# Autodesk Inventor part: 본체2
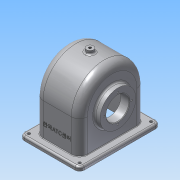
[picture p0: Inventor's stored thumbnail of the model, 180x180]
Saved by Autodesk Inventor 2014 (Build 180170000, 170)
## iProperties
Created: 2016-01
Part Number: 본체2
Material: 알루미늄 6061
Document SubType Name: Modeling
Designer: User
Mass: 842.835 g
Surface Area: 990.698 cm^2
Volume: 311.009 cm^3
Density: 2.71 g/cm^3
Appearance: 알루미늄 - 평지
Author: User
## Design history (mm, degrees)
sketch "스케치1"
  geometry: L1 (-57, 0)-(57, 0); L2 (57, 0)-(57, -64); L3 (57, -64)-(-57, -64); L4 (-57, -64)-(-57, 0); C1 r 57 at (0, 0); 2 further points
  constraints: 8 end point, 2 coincident, 2 parallel, 1 centre point, 1 horizontal, 1 midpoint, 1 perpendicular
  dimensions: "d0" = 114 diameter of C1; "d1" = 114 distance of L2.end L3.end; "d2" = 64 distance of L1.end L2.end
extrude "돌출1" new body sketch "스케치1" stored distance "d3" = 77; taper "d4" = 0 deg
feature "쉘1" dims "d7" = 6
sketch "스케치3"
  geometry: L1 (114, 0)-(114, -77) reference; L2 (0, 0)-(114, 0) reference; L3 (0, 0)-(0, -77) reference; L4 (114, -77)-(0, -77) reference; L5 (-13, 13.5)-(127, 13.5); L6 (127, 13.5)-(127, -90.5); L7 (127, -90.5)-(-13, -90.5); L8 (-13, -90.5)-(-13, 13.5); 3 further points
  constraints: 8 end point, 2 midpoint, 2 parallel, 1 horizontal, 1 horizontal alignment, 1 perpendicular, 1 vertical alignment
  dimensions: "d8" = 140 distance of L5.start L5.end; "d9" = 104 distance of L5.end L6.end
extrude "돌출2" join sketch "스케치3" distance "d10" = 7; taper "d11" = 0 deg
fillet "모깎기1" dims "d12" = 14
node "작업 평면1"
sketch "스케치6"
  geometry: C1 r 6 at (0, 0); 1 further point
  constraints: 1 centre point, 1 coincident
  dimensions: "d36" = 12 diameter of C1
extrude "돌출4" join sketch "스케치6" stored distance "d37" = 10; taper "d38" = 0 deg
hole "구멍2" diameter "d41" = 4.459; stored, may be unused: countersink angle "d45" = 90 deg, drill point angle "d47" = 118 deg; dims "d39" = 10, "d40" = 10, "d42" = 6, "d43" = 4, "d44" = 2, "d46" = 63
fillet "모깎기4" dims "d77" = 8
sketch "스케치9"
  geometry: A1 r 8 centre (119, 82.5) between (127, 82.5) and (119, 90.5) reference; A2 r 8 centre (-5, 82.5) between (-5, 90.5) and (-13, 82.5) reference; A3 r 8 centre (-5, -5.5) between (-13, -5.5) and (-5, -13.5) reference; A4 r 8 centre (119, -5.5) between (119, -13.5) and (127, -5.5) reference; 1 further point
hole "구멍5" sketch "스케치9" at (119, 82.5), (-5, 82.5), (119, -5.5), (-5, -5.5) diameter "d78" = 5; stored, may be unused: countersink angle "d82" = 90 deg, drill point angle "d84" = 118 deg; dims "d79" = 7, "d80" = 4, "d81" = 2, "d83" = 9
fillet "모깎기5" dims "d85" = 3
sketch "스케치10"
  geometry: L1 (49, 0)-(49, -57) reference; L2 (0, 0)-(49, 0) reference; L3 (0, -57)-(0, 0) reference; L4 (-1.387, -30.398)-(50.387, -30.398); L5 (50.387, -30.398)-(50.387, -37.602); L6 (50.387, -37.602)-(-1.387, -37.602); L7 (-1.387, -37.602)-(-1.387, -30.398); L8 (0, -34)-(49, -34); L9 (-19.5, -64)-(68.5, -64) reference; L10 (24.5, 0)-(24.5, -54); L11 (-14, 0)-(-14, -57) reference; L12 (68.5, -57)-(-19.5, -57) reference; 4 further points
  constraints: 4 end point, 4 midpoint, 2 point on line, 1 horizontal alignment, 1 perpendicular, 1 vertical alignment, 2 other
  dimensions: "d86" = 30 distance between parallel lines of L9 L8; "d87" = 38.5 distance between parallel lines of L11 L10
feature "엠보싱1" sketch "스케치10" dims "d8" = 140, "d9" = 104, "d88" = 0.5, "d89" = 0
sketch "스케치11"
  geometry: L1 (-51, -64)-(-51, 0) reference; L2 (51, -64)-(-51, -64) reference; L3 (51, 0)-(51, -64) reference; C1 r 20 at (0, -4) reference; A1 r 51 centre (0, 0) between (51, 0) and (-51, 0) reference
extrude "돌출5" cut sketch "스케치11" distance "d90" = 1; taper "d91" = 0 deg
sketch "스케치12"
  geometry: L1 (-51, -64)-(-51, 0) reference; L2 (51, -64)-(-51, -64) reference; L3 (51, 0)-(51, -64) reference; C1 r 38.908 at (0, -4) reference; A1 r 51 centre (0, 0) between (51, 0) and (-51, 0) reference
extrude "돌출6" cut sketch "스케치12" distance "d92" = 1; taper "d93" = 0 deg
sketch "스케치13"
  geometry: L1 (-4, 43.197)-(-4, -48.942); L2 (-64, -33.5)-(-64, 33.5) reference; L3 (16, 35.5)-(30.899, 35.5); L4 (24, 35.5)-(24, 19.5); L5 (24, 19.5)-(16, 19.5); L6 (16, 19.5)-(16, 35.5); L7 (0, 38.5)-(43, 38.5) reference; L8 (24, 19.5)-(39.943, 38.5); L9 (30.899, 35.5)-(33.416, 38.5); L10 (-4, 33.5)-(16, 33.5); L11 (-4, 38.5)-(33.416, 38.5); L12 (-4, 38.5)-(-4, 33.5); 1 further point
  constraints: 20 end point, 6 point on line, 3 parallel, 2 perpendicular, 1 collinear, 1 horizontal, 1 vertical
  dimensions: "d95" = 60 distance between parallel lines of L1 L2; "d96" = 20 distance between parallel lines of L1 L6; "d99" = 50 deg angle of L8 L5; "d100" = 5 distance between parallel lines of L8 L9; "d102" = 5 distance between parallel lines of L10 L11; "d103" = 56 diameter of L4 L1; "d104" = 19 distance between parallel lines of L11 L5; "d105" = 3 distance between parallel lines of L11 L3
revolve "회전3" stored, may be unused: angle "d106" = 90 deg
revolve "회전4" stored, may be unused: angle "d107" = 90 deg
sketch "스케치14"
  geometry: C1 r 20 at (0, -4) reference; C2 r 31 at (0, -4)
  constraints: 1 centre point, 1 coincident
  dimensions: "d108" = 62 diameter of C2
extrude "돌출7" join sketch "스케치14" distance "d109" = 10; taper "d110" = 0 deg
hole "구멍6" diameter "d113" = 40; stored, may be unused: countersink angle "d117" = 90 deg, drill point angle "d119" = 118 deg; dims "d111" = 10, "d112" = 10, "d114" = 6, "d115" = 4, "d116" = 2, "d118" = 8
chamfer "모따기3" distance "d120" = 1; stored, may be unused: second distance "d121" = 2, angle "d122" = 45 deg
fillet "모깎기6" dims "d123" = 3
sketch "스케치15"
  geometry: C1 r 31 at (0, 0) reference; 2 further points
  constraints: 1 vertical alignment
  dimensions: "d124" = 24 distance of C1.centre point (0, 24)
hole "구멍7" sketch "스케치15" at (0, 24) diameter "d125" = 2.459; stored, may be unused: countersink angle "d129" = 90 deg, drill point angle "d131" = 118 deg; dims "d126" = 6, "d127" = 4, "d128" = 2, "d130" = 8
sketch "스케치16"
  geometry: C1 r 21 at (0, 0) reference; 2 further points
  constraints: 1 vertical alignment
  dimensions: "d135" = 28 distance of C1.centre point (0, 28)
hole "구멍8" sketch "스케치16" at (0, 28) diameter "d136" = 2.459; stored, may be unused: countersink angle "d140" = 90 deg, drill point angle "d142" = 118 deg; dims "d137" = 7, "d138" = 4, "d139" = 2, "d141" = 9
fillet "모깎기7" dims "d146" = 9
fillet "모깎기8" dims "d147" = 3
fillet "모깎기9" dims "d148" = 1
node "솔리드1"
pattern_circular "원형 패턴3" dims angle "d133" = 360 deg
pattern_circular "원형 패턴4" dims angle "d144" = 360 deg
other parameters: "d35" = 63
